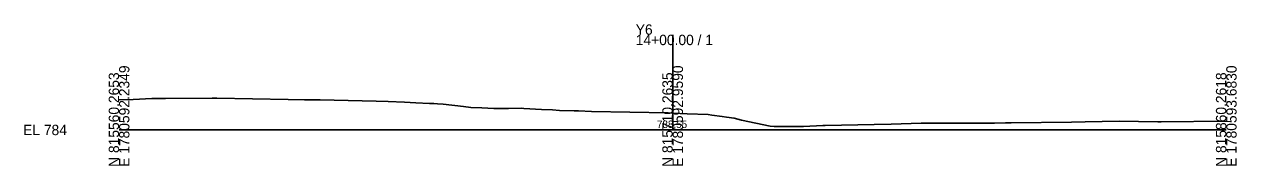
# Model space of a CAD drawing. Extents: x -26 to 1603, y -10 to 6024.
# Drawn here: x -25.7 to 302.8, y 5490.3 to 5528.6 of the extents above; entities that cross this region are included whole.
import ezdxf

# ---------------------------------------------------------------- set-up
doc = ezdxf.new("R2010")
doc.units = 0
for name, color, linetype in [('Exist Cross Section Cell', 7, 'Continuous'), ('Exist XS Center Line Elevation Label', 7, 'Continuous'), ('Exist XS Ground Line', 7, 'Continuous')]:
    doc.layers.add(name, color=color, linetype=linetype)

msp = doc.modelspace()

# ---------------------------------------------------------------- linework, layer by layer
at = {"layer": 'Exist Cross Section Cell'}
for p, q in [((150, 5500), (150, 5525.8)), ((0, 5500), (150, 5500)), ((150, 5500), (300, 5500))]:
    msp.add_line(p, q, dxfattribs=at)
at = {"layer": 'Exist XS Ground Line'}
for p, q in [((0, 5508.13), (3.85, 5508.3)), ((3.85, 5508.3), (8.86, 5508.54)), ((8.86, 5508.54), (10.4, 5508.55)), ((10.4, 5508.55), (12.61, 5508.57)), ((12.61, 5508.57), (25.2, 5508.6)), ((25.2, 5508.6), (25.72, 5508.6)), ((25.72, 5508.6), (26.5, 5508.59)), ((26.5, 5508.59), (45.83, 5508.3)), ((45.83, 5508.3), (50.28, 5508.21)), ((50.28, 5508.21), (54.53, 5508.13)), ((54.53, 5508.13), (69.67, 5507.83)), ((69.67, 5507.83), (72.93, 5507.71)), ((72.93, 5507.71), (77.31, 5507.54)), ((77.31, 5507.54), (80.39, 5507.39)), ((80.39, 5507.39), (84.09, 5507.2)), ((84.09, 5507.2), (85.28, 5507.14)), ((85.28, 5507.14), (86.27, 5507.09)), ((86.27, 5507.09), (87.79, 5507.01)), ((87.79, 5507.01), (93.36, 5506.35)), ((93.36, 5506.35), (95.32, 5506.08)), ((95.32, 5506.08), (98.26, 5505.96)), ((98.26, 5505.96), (101.52, 5505.84)), ((101.52, 5505.84), (103.31, 5505.8)), ((103.31, 5505.8), (105.54, 5505.84)), ((105.54, 5505.84), (109.15, 5505.88)), ((109.15, 5505.88), (109.65, 5505.85)), ((109.65, 5505.85), (114.42, 5505.58)), ((114.42, 5505.58), (117.47, 5505.42)), ((117.47, 5505.42), (119.34, 5505.31)), ((119.34, 5505.31), (123.29, 5505.21)), ((123.29, 5505.21), (124.47, 5505.19)), ((124.47, 5505.19), (128.03, 5505.05)), ((128.03, 5505.05), (148.77, 5504.61)), ((148.77, 5504.61), (150, 5504.55)), ((150, 5504.55), (153.93, 5504.37)), ((153.93, 5504.37), (159.66, 5504.15)), ((159.66, 5504.15), (160.6, 5504.05)), ((160.6, 5504.05), (163.41, 5503.67)), ((163.41, 5503.67), (164.61, 5503.44)), ((164.61, 5503.44), (166.62, 5503.19)), ((166.62, 5503.19), (168.65, 5502.64)), ((168.65, 5502.64), (176.39, 5501.05)), ((176.39, 5501.05), (177.5, 5500.9)), ((177.5, 5500.9), (184.88, 5500.95)), ((184.88, 5500.95), (185.48, 5500.95)), ((185.48, 5500.95), (190.67, 5501.21)), ((190.67, 5501.21), (191.34, 5501.23)), ((191.34, 5501.23), (204.62, 5501.49)), ((204.62, 5501.49), (209.24, 5501.59)), ((209.24, 5501.59), (217.34, 5501.81)), ((217.34, 5501.81), (223.94, 5501.83)), ((223.94, 5501.83), (237.22, 5501.86)), ((237.22, 5501.86), (240.14, 5501.9)), ((240.14, 5501.9), (241.7, 5501.92)), ((241.7, 5501.92), (258.04, 5502.16)), ((258.04, 5502.16), (261.79, 5502.25)), ((261.79, 5502.25), (270.97, 5502.4)), ((270.97, 5502.4), (281.46, 5502.21)), ((281.46, 5502.21), (281.86, 5502.21)), ((281.86, 5502.21), (282.36, 5502.22)), ((282.36, 5502.22), (300, 5502.42))]:
    msp.add_line(p, q, dxfattribs=at)

# ---------------------------------------------------------------- texts
at = {"layer": 'Exist Cross Section Cell'}
for s, p in [('Y6', (140, 5525.8)), ('14+00.00 / 1', (140, 5523)), ('EL 784', (-26, 5498.6))]:
    msp.add_text(s, height=2.8, dxfattribs=at).set_placement(p)
for s, p in [('E 1780592.2349', (2.8, 5490)), ('E 1780592.9590', (152.8, 5490)), ('E 1780593.6830', (302.8, 5490)), ('N 815560.2653', (0, 5490)), ('N 815710.2635', (150, 5490)), ('N 815860.2618', (300, 5490))]:
    msp.add_text(s, height=2.8, rotation=90, dxfattribs=at).set_placement(p)
at = {"layer": 'Exist XS Center Line Elevation Label'}
msp.add_text('788.55', height=2, dxfattribs=at).set_placement((145.74, 5500.55))

doc.saveas('drawing.dxf')
